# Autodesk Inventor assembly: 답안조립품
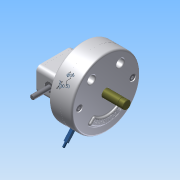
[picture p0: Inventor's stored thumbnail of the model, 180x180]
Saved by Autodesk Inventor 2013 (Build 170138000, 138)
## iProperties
Created: 2015-04
Part Number: 답안조립품
Document SubType Name: Assembly
Designer: Administrator
Mass: 3993.65 g
Surface Area: 3333.7 cm^2
Volume: 1144.5 cm^3
Density: 3.48944 g/cm^3
Author: Administrator
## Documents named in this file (15)
- C:\Documents and Settings\Administrator\바탕 화면\350405V1022\답안조립품.iam
- C:\Documents and Settings\Administrator\바탕 화면\350405V1022\본체.ipt
- C:\Documents and Settings\Administrator\바탕 화면\350405V1022\커버2.ipt
- C:\Documents and Settings\Administrator\바탕 화면\350405V1022\베어링62_22.ipt
- C:\Documents and Settings\Administrator\바탕 화면\350405V1022\축.ipt
- C:\Documents and Settings\Administrator\바탕 화면\350405V1022\M 5 x 12.ipt
- C:\Documents and Settings\Administrator\바탕 화면\350405V1022\부시.ipt
- C:\Documents and Settings\Administrator\바탕 화면\350405V1022\슬라이더3.ipt
- C:\Documents and Settings\Administrator\바탕 화면\350405V1022\슬라이더2.ipt
- C:\Documents and Settings\Administrator\바탕 화면\350405V1022\멈춤링.ipt
- C:\Documents and Settings\Administrator\바탕 화면\350405V1022\슬라이더.ipt
- C:\Documents and Settings\Administrator\바탕 화면\350405V1022\평행핀.ipt
- C:\Documents and Settings\Administrator\바탕 화면\350405V1022\커버.ipt
- C:\Documents and Settings\Administrator\바탕 화면\350405V1022\M 10 x 35.ipt
- C:\Documents and Settings\Administrator\바탕 화면\350405V1022\가변스프링.ipt
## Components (6 placed, 4 different names)
1. M 5 x 12:1
2. M 5 x 12:2
3. KS B 1320 B B 5 x  20:1 — 플러쉬:2
4. M 10 x 35:1
5. M 10 x 35:2
6. 가변스프링:1
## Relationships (1: Flush 1)
- 플러쉬:2 [Flush]: KS B 1320 B B 5 x  20:1
